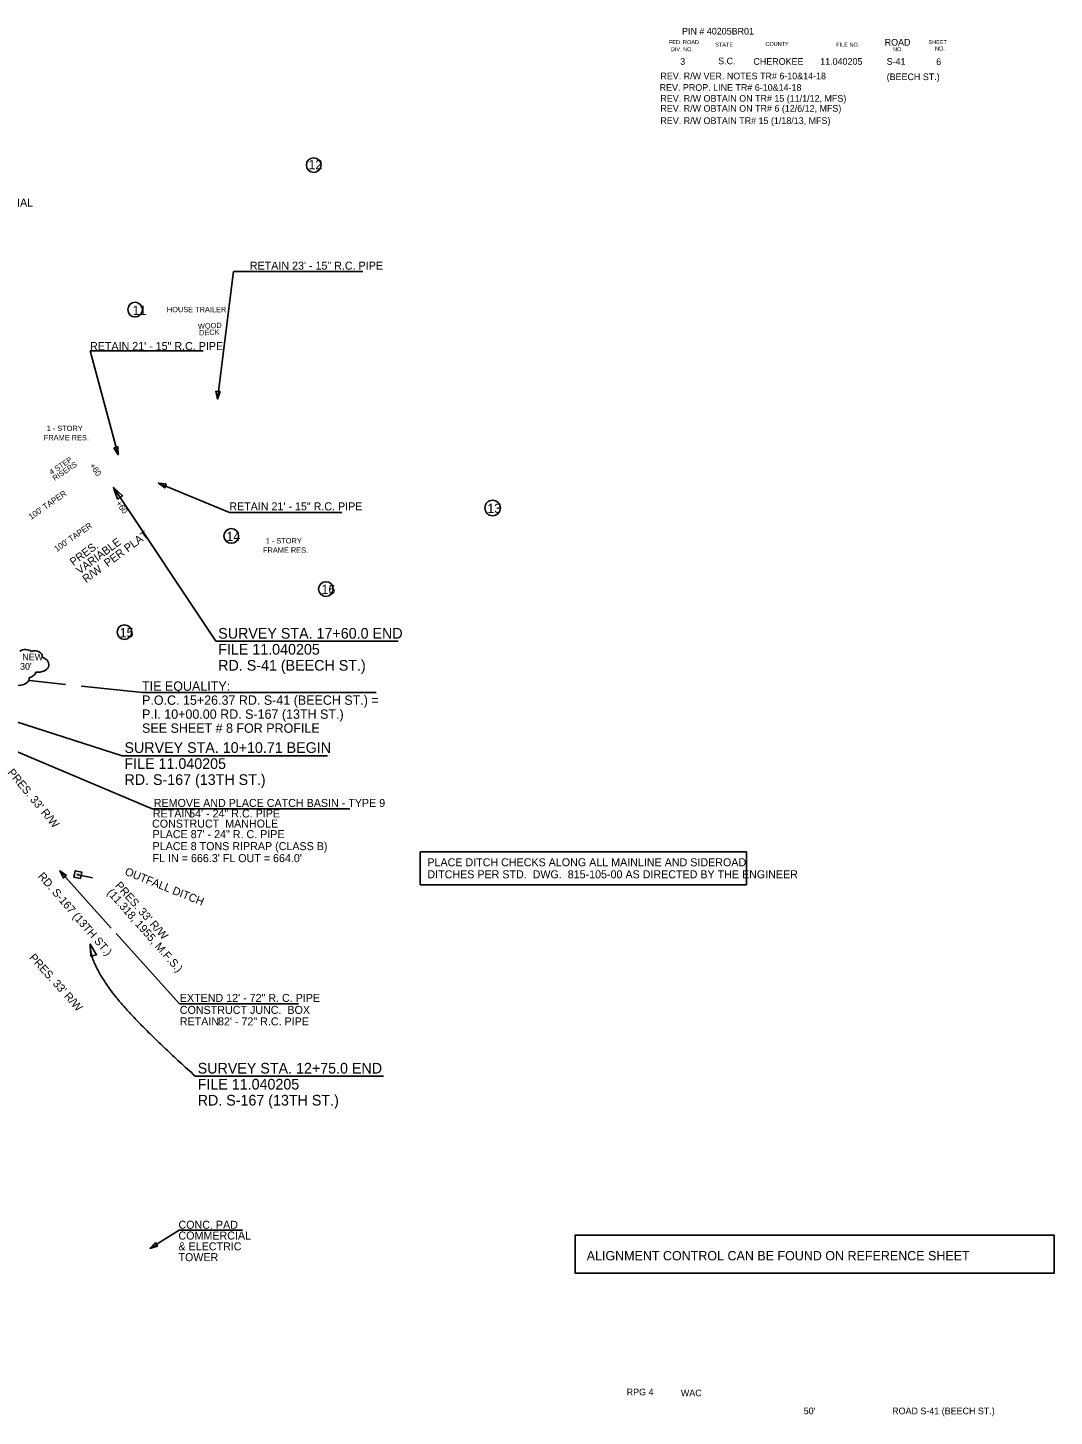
# Model space of a CAD drawing. Extents: x 16382402 to 16388022, y 46194326 to 46202918.
# Drawn here: x 16385170 to 16385940, y 46194463 to 46195505 of the extents above; entities that cross this region are included whole.
import ezdxf

# ---------------------------------------------------------------- set-up
doc = ezdxf.new("R2010")
doc.units = 0
for name, color, linetype in [('RD_EX_DR_Inlet', 7, 'Continuous'), ('RD_EX_DV_Prop', 7, 'Continuous'), ('RD_EX_GuardRail', 7, 'Continuous'), ('RD_EX_Misc', 7, 'Continuous'), ('RD_EX_RW_TX', 7, 'Continuous'), ('RD_HC_Data', 7, 'Continuous'), ('RD_PD_ALT1_TrvlWay', 7, 'Continuous'), ('RD_PD_Final_TX', 7, 'Continuous'), ('RD_PD_RW_TX', 7, 'Continuous'), ('RD_SHT_TX', 7, 'Continuous'), ('RD_Sketch1', 7, 'Continuous'), ('RD_TX_Bldg', 7, 'Continuous'), ('RD_TX_Drainage', 7, 'Continuous'), ('RD_TX_RoadID', 7, 'Continuous')]:
    doc.layers.add(name, color=color, linetype=linetype)

msp = doc.modelspace()

# ---------------------------------------------------------------- linework, layer by layer
at = {"layer": 'RD_EX_DR_Inlet'}
msp.add_line((16385209.6, 46194866.6), (16385210.6, 46194871.5), dxfattribs=at)
msp.add_lwpolyline([(16385209.6, 46194866.6), (16385210.6, 46194871.5), (16385205.7, 46194872.5), (16385204.7, 46194867.6)], close=True, dxfattribs=at)
at = {"layer": 'RD_EX_DV_Prop'}
for centre, radius in [((16385384.5, 46195401.6), 5.49), ((16385250.6, 46195293.2), 5.49), ((16385518.6, 46195144.5), 5.81), ((16385322.7, 46195123.5), 5.49), ((16385393.6, 46195083.7), 5.49), ((16385242.6, 46195051.4), 5.49)]:
    msp.add_circle(centre, radius, dxfattribs=at)
at = {"layer": 'RD_EX_GuardRail'}
for q in [(16385261.7, 46194589.3), (16385331.1, 46194602.9)]:
    msp.add_line((16385283.7, 46194602.9), q, dxfattribs=at)
at = {"layer": 'RD_HC_Data'}
for p, q in [((16385171.5, 46195015), (16385198.5, 46195012.1)), ((16385210.4, 46195010.8), (16385256.1, 46195006)), ((16385256.1, 46195006), (16385431.3, 46195006))]:
    msp.add_line(p, q, dxfattribs=at)
at = {"layer": 'RD_PD_Final_TX'}
for p, q in [((16385234.3, 46195159.9), (16385311.1, 46195044.5)), ((16385311.1, 46195044.5), (16385447.7, 46195044.5)), ((16385240.9, 46194958.7), (16385047.9, 46195020.6)), ((16385240.9, 46194958.7), (16385394.9, 46194958.7)), ((16385295.7, 46194718.4), (16385436.9, 46194718.4))]:
    msp.add_line(p, q, dxfattribs=at)
msp.add_open_spline([(16385217, 46194817.5), (16385216, 46194805.6), (16385247.2, 46194762), (16385295.7, 46194718.4)], degree=2, dxfattribs=at)
at = {"layer": 'RD_PD_RW_TX'}
for centre, major_axis, ratio, start_param, end_param in [((16385168, 46195032.9), (-7.08, -0.7), 0.755788, 3.867404, 5.222922), ((16385175.3, 46195032.9), (-5.79, -0.16), 0.773799, 3.031897, 5.10833), ((16385177, 46195027.4), (9.02, -0.72), 0.66589, 4.686726, 7.435411), ((16385162.2, 46195017.5), (9.02, -0.72), 0.66589, 3.403955, 6.32995), ((16385169.3, 46195022.2), (-7.08, -0.7), 0.755788, 1.767761, 2.866116)]:
    msp.add_ellipse(centre, major_axis=major_axis, ratio=ratio, start_param=start_param, end_param=end_param, dxfattribs=at)
at = {"layer": 'RD_Sketch1'}
msp.add_lwpolyline([(16385580.4, 46194599.1), (16385939.6, 46194599.1), (16385939.6, 46194570.8), (16385580.4, 46194570.8)], close=True, dxfattribs=at)
at = {"layer": 'RD_TX_Drainage'}
for p, q in [((16385312.3, 46195226.2), (16385324.4, 46195321.7)), ((16385421.3, 46195321.7), (16385324.4, 46195321.7)), ((16385301.5, 46195262.4), (16385216.8, 46195262.4)), ((16385237.9, 46195184.4), (16385216.8, 46195262.4)), ((16385268.1, 46195163.2), (16385321.3, 46195141.2)), ((16385405.6, 46195141.2), (16385321.3, 46195141.2)), ((16385263.5, 46194919), (16385102, 46194986.9)), ((16385411.5, 46194919), (16385263.5, 46194919)), ((16385194.1, 46194872.3), (16385232.7, 46194829.4)), ((16385218.6, 46194867.2), (16385206.8, 46194869.6)), ((16385209.6, 46194866.6), (16385210.6, 46194871.5)), ((16385236.3, 46194825.4), (16385283.8, 46194772.7)), ((16385373.1, 46194772.7), (16385283.8, 46194772.7))]:
    msp.add_line(p, q, dxfattribs=at)
for points in [[(16385311.2, 46195232.1), (16385312.3, 46195226.2), (16385314.3, 46195231.8)], [(16385234.7, 46195189.5), (16385237.9, 46195184.4), (16385237.7, 46195190.4)], [(16385237.4, 46195151.2), (16385234.3, 46195159.9), (16385241.2, 46195153.6)], [(16385274, 46195162.5), (16385268.1, 46195163.2), (16385272.9, 46195159.6)], [(16385464.4, 46194886.6), (16385708.9, 46194886.6), (16385708.9, 46194862), (16385464.4, 46194862)], [(16385199.1, 46194869), (16385194.1, 46194872.3), (16385196.8, 46194866.9)], [(16385209.6, 46194866.6), (16385210.6, 46194871.5), (16385205.7, 46194872.5), (16385204.7, 46194867.6)], [(16385217.4, 46194808.3), (16385217, 46194817.5), (16385221.7, 46194809.5)], [(16385265.8, 46194593.7), (16385261.7, 46194589.3), (16385267.4, 46194591)]]:
    msp.add_lwpolyline(points, close=True, dxfattribs=at)

# ---------------------------------------------------------------- texts
at = {"layer": 'RD_EX_DR_Inlet'}
msp.add_text('JB', height=1.87, rotation=348.3223, dxfattribs=at).set_placement((16385206, 46194868.8))
at = {"layer": 'RD_EX_DV_Prop'}
for s, p in [('12', (16385380.6, 46195398.5)), ('11', (16385248.7, 46195289.3)), ('13', (16385514.6, 46195140.7)), ('14', (16385319, 46195119.7)), ('16', (16385390.3, 46195080)), ('15', (16385239, 46195047.5))]:
    msp.add_text(s, height=7, dxfattribs=at).set_placement(p)
at = {"layer": 'RD_EX_GuardRail'}
for s, p in [('COMMERCIAL ', (16385119.8, 46195370.5)), ('CONC. PAD', (16385283.1, 46194604)), ('COMMERCIAL ', (16385283.1, 46194595.9)), ('& ELECTRIC', (16385283.1, 46194587.8)), ('TOWER', (16385283.1, 46194579.7))]:
    msp.add_text(s, height=6, dxfattribs=at).set_placement(p)
at = {"layer": 'RD_EX_Misc'}
for s, p in [('PIN # 40205BR01', (16385660.6, 46195499.5)), ('ROAD', (16385812.5, 46195491.2)), ('CHEROKEE', (16385714.1, 46195476.8)), ('11.040205 ', (16385764.2, 46195476.8)), ('S-41', (16385814, 46195476.8)), ('6', (16385851.1, 46195476.6)), ('(BEECH ST.)', (16385814, 46195465.3)), ('RPG 4', (16385619.1, 46194479.1)), ('WAC', (16385659.7, 46194478.4)), ("50'                               ROAD S-41 (BEECH ST.)", (16385751.8, 46194464.9))]:
    msp.add_text(s, height=5, dxfattribs=at).set_placement(p)
at = {"layer": 'RD_EX_RW_TX'}
for s, rotation, p in [('VARIABLE ', 36.4852, (16385209.1, 46195094.4)), ('R/W  PER PLAT', 36.4852, (16385213.9, 46195088)), ('PRES. ', 36.4852, (16385204.4, 46195100.8)), ("PRES. 33' R/W ", 309.6469, (16385154.7, 46194945.9)), ('(11.318, 1955, M.F.S.)', 311.5486, (16385229.2, 46194855.8)), ("PRES. 33' R/W ", 311.5486, (16385235.2, 46194861.1)), ("PRES. 33' R/W ", 312.0514, (16385170.8, 46194807))]:
    msp.add_text(s, height=6, rotation=rotation, dxfattribs=at).set_placement(p)
at = {"layer": 'RD_HC_Data'}
for s, p in [('TIE EQUALITY:', (16385255.8, 46195007.4)), ('P.O.C. 15+26.37 RD. S-41 (BEECH ST.) =', (16385255.8, 46194996.9)), ('P.I. 10+00.00 RD. S-167 (13TH ST.)', (16385255.8, 46194986.4)), ('SEE SHEET # 8 FOR PROFILE', (16385255.8, 46194975.9))]:
    msp.add_text(s, height=7, dxfattribs=at).set_placement(p)
at = {"layer": 'RD_PD_ALT1_TrvlWay'}
for s, rotation, p in [('+60', 304.9044, (16385216.2, 46195176.2)), ("100' TAPER", 34.9044, (16385172.7, 46195135.5)), ('+60', 304.9044, (16385236, 46195148)), ("100' TAPER", 34.9044, (16385191.9, 46195111.4))]:
    msp.add_text(s, height=4.5, rotation=rotation, dxfattribs=at).set_placement(p)
at = {"layer": 'RD_PD_Final_TX'}
for s, p in [('SURVEY STA. 17+60.0 END', (16385312.9, 46195046.5)), ('FILE 11.040205', (16385312.9, 46195034.5)), ('RD. S-41 (BEECH ST.)', (16385312.9, 46195022.5)), ('SURVEY STA. 10+10.71 BEGIN', (16385242.6, 46194960.8)), ('FILE 11.040205', (16385242.6, 46194948.8)), ('RD. S-167 (13TH ST.)', (16385242.6, 46194936.8)), ('SURVEY STA. 12+75.0 END', (16385297.5, 46194720.4)), ('FILE 11.040205', (16385297.5, 46194708.4)), ('RD. S-167 (13TH ST.)', (16385297.5, 46194696.4))]:
    msp.add_text(s, height=8, dxfattribs=at).set_placement(p)
at = {"layer": 'RD_PD_RW_TX'}
for s, p in [('OBT.  NEW', (16385146.7, 46195030.2)), ("30'  X 30'", (16385145.6, 46195023.2))]:
    msp.add_text(s, height=5, dxfattribs=at).set_placement(p)
at = {"layer": 'RD_SHT_TX'}
for s, height, p in [('FED. ROAD', 3, (16385650.7, 46195492.3)), ('STATE', 3, (16385685.5, 46195490.4)), ('COUNTY', 3, (16385723.1, 46195490.9)), ('FILE NO.', 3, (16385776.2, 46195490.4)), ('SHEET', 3, (16385845.3, 46195492.3)), ('DIV. NO.', 3, (16385652.2, 46195487)), ('S.C.', 5, (16385687.7, 46195477.2)), ('NO.', 3, (16385818.8, 46195487)), ('NO.', 3, (16385850.2, 46195487.5)), ('3', 5, (16385659.2, 46195476.8)), ('REV. PROP. LINE TR# 6-10&14-18', 5, (16385643.8, 46195457.3)), ('REV. R/W VER. NOTES TR# 6-10&14-18', 5, (16385644.4, 46195465.9)), ('REV. R/W OBTAIN ON TR# 15 (11/1/12, MFS)', 5, (16385644.4, 46195449.1)), ('REV. R/W OBTAIN ON TR# 6 (12/6/12, MFS)', 5, (16385644.4, 46195441.6)), ('REV. R/W OBTAIN TR# 15 (1/18/13, MFS)', 5, (16385644.4, 46195432.4))]:
    msp.add_text(s, height=height, dxfattribs=at).set_placement(p)
at = {"layer": 'RD_Sketch1'}
msp.add_text('ALIGNMENT CONTROL CAN BE FOUND ON REFERENCE SHEET', height=7, dxfattribs=at).set_placement((16385589.1, 46194580.3))
at = {"layer": 'RD_TX_Bldg'}
for s, p in [('HOUSE TRAILER', (16385274.4, 46195291.3)), ('1 - STORY', (16385184.3, 46195202.2)), ('FRAME RES.', (16385182.2, 46195195.2)), ('1 - STORY', (16385348.5, 46195117.9)), ('FRAME RES.', (16385346.5, 46195110.9))]:
    msp.add_text(s, height=4, dxfattribs=at).set_placement(p)
for s, rotation, p in [('WOOD', 2.6657, (16385297.8, 46195278.7)), ('DECK', 2.6657, (16385298.6, 46195273.8)), ('4 STEP', 33.7999, (16385188, 46195169.2)), ('RISERS', 33.7999, (16385190.4, 46195164.7))]:
    msp.add_text(s, height=4, rotation=rotation, dxfattribs=at).set_placement(p)
at = {"layer": 'RD_TX_Drainage'}
for s, p in [('RETAIN 23\' - 15" R.C. PIPE', (16385336.6, 46195323.2)), ('RETAIN 21\' - 15" R.C. PIPE', (16385216.8, 46195262.9)), ('RETAIN 21\' - 15" R.C. PIPE', (16385321.2, 46195142.7)), ('REMOVE AND PLACE CATCH BASIN - TYPE 9', (16385264.6, 46194920.3)), ('CONSTRUCT  MANHOLE', (16385263.3, 46194904.8)), ('RETAIN', (16385263.9, 46194912.4)), ('54\' - 24" R.C. PIPE', (16385291.1, 46194912.4)), ('PLACE 87\' - 24" R. C. PIPE', (16385263.7, 46194896.9)), ('PLACE 8 TONS RIPRAP (CLASS B)', (16385263.7, 46194887.9)), ("FL IN = 666.3' FL OUT = 664.0'", (16385263.7, 46194878.9)), ('PLACE DITCH CHECKS ALONG ALL MAINLINE AND SIDEROAD ', (16385469.7, 46194875.8)), ('DITCHES PER STD.  DWG.  815-105-00 AS DIRECTED BY THE ENGINEER', (16385469.7, 46194866.8)), ('EXTEND 12\' - 72" R. C. PIPE', (16385284.1, 46194774.1)), ('CONSTRUCT JUNC.  BOX', (16385284.1, 46194765.1)), ('RETAIN', (16385284.1, 46194756.5)), ('     82\' - 72" R.C. PIPE', (16385301.6, 46194756.5))]:
    msp.add_text(s, height=6, dxfattribs=at).set_placement(p)
msp.add_text('JB', height=1.87, rotation=348.3223, dxfattribs=at).set_placement((16385206, 46194868.8))
at = {"layer": 'RD_TX_RoadID'}
for s, rotation, p in [('RD. S-167 (13TH ST.)', 310.899, (16385177.4, 46194868.1)), ('OUTFALL DITCH', 338.0984, (16385242.4, 46194869.6))]:
    msp.add_text(s, height=6, rotation=rotation, dxfattribs=at).set_placement(p)

doc.saveas('drawing.dxf')
